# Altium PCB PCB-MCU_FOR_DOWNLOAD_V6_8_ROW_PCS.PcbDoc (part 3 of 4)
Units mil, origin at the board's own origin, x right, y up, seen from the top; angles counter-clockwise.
Board outline not stored, 4 copper layers (Top, GND1, GND2, Bottom), stack 35.4 mil thick; 280 components, 38 nets, 1144 pads, 944 vias.
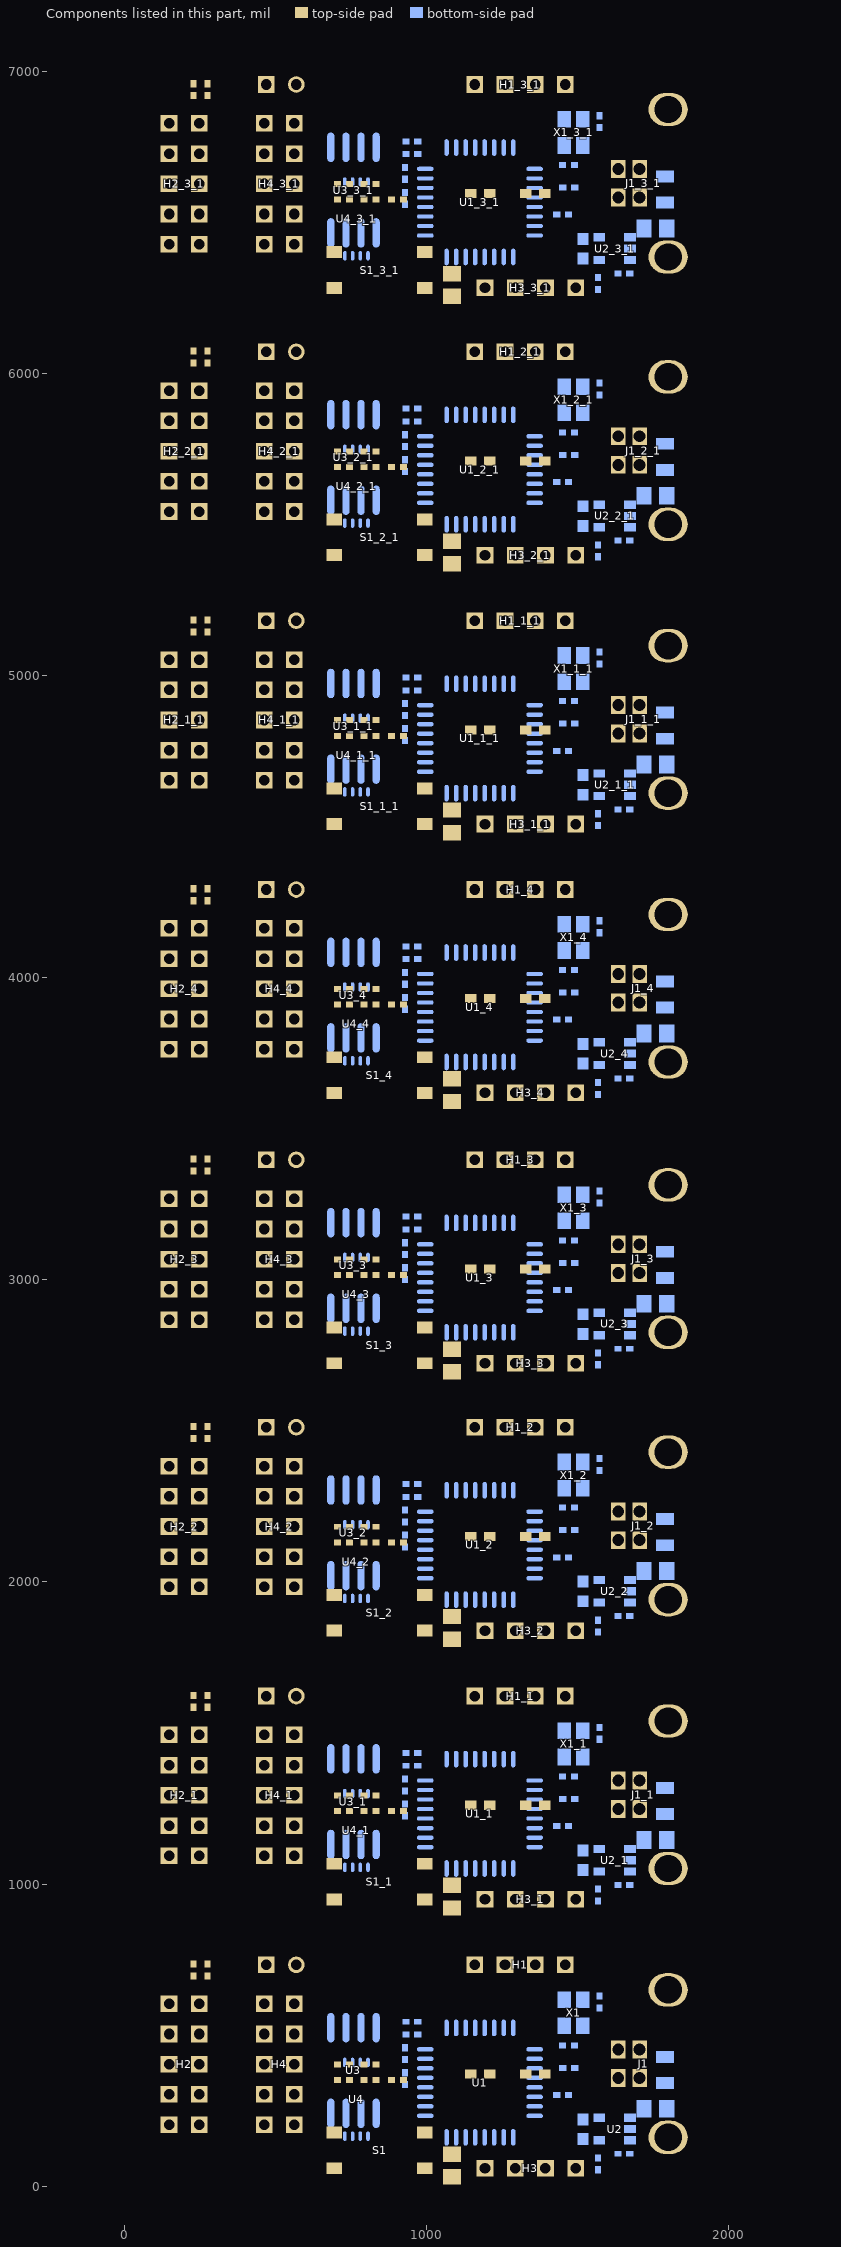
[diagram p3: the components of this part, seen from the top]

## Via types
v1: diameter 16/16/16/16 (per signal layer), hole 8, Top to Bottom, 936 vias
v2: diameter 55/55/55/55 (per signal layer), hole 37, Top to Bottom, 8 vias

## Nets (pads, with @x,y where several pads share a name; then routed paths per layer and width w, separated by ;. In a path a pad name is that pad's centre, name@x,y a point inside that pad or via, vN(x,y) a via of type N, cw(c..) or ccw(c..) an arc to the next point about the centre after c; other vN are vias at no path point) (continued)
copper on no net: (continued)
  Bottom w7.87: 146.85,1393.54 194.88,1441.57 413.78,1441.57 461.81,1393.54 508.27,1440 509.06,1440 509.84,1440.79 582.68,1440.79 601.57,1459.69 601.57,1497.09 637.4,1532.91 878.74,1532.91 966.14,1445.51 966.14,1434.09 966.14,1432.91 968.9,1432.91 970.08,1434.09 970.08,1391.58 970.08,1389.61 928.35,1347.87 ; 146.85,2283.54 194.88,2331.57 413.78,2331.57 461.81,2283.54 508.27,2330 509.06,2330 509.84,2330.79 582.68,2330.79 601.57,2349.69 601.57,2387.09 637.4,2422.91 878.74,2422.91 966.14,2335.51 966.14,2324.09 966.14,2322.91 968.9,2322.91 970.08,2324.09 970.08,2281.58 970.08,2279.61 928.35,2237.87 ; 146.85,3168.54 194.88,3216.57 413.78,3216.57 461.81,3168.54 508.27,3215 509.06,3215 509.84,3215.79 582.68,3215.79 601.57,3234.69 601.57,3272.09 637.4,3307.91 878.74,3307.91 966.14,3220.51 966.14,3209.09 966.14,3207.91 968.9,3207.91 970.08,3209.09 970.08,3166.58 970.08,3164.61 928.35,3122.87 ; 146.85,4063.54 194.88,4111.57 413.78,4111.57 461.81,4063.54 508.27,4110 509.06,4110 509.84,4110.79 582.68,4110.79 601.57,4129.69 601.57,4167.09 637.4,4202.91 878.74,4202.91 966.14,4115.51 966.14,4104.09 966.14,4102.91 968.9,4102.91 970.08,4104.09 970.08,4061.58 970.08,4059.61 928.35,4017.87 ; 146.85,4953.54 194.88,5001.57 413.78,5001.57 461.81,4953.54 508.27,5000 509.06,5000 509.84,5000.79 582.68,5000.79 601.57,5019.69 601.57,5057.09 637.4,5092.91 878.74,5092.91 966.14,5005.51 966.14,4994.09 966.14,4992.91 968.9,4992.91 970.08,4994.09 970.08,4951.58 970.08,4949.61 928.35,4907.87 ; 146.85,5843.54 194.88,5891.57 413.78,5891.57 461.81,5843.54 508.27,5890 509.06,5890 509.84,5890.79 582.68,5890.79 601.57,5909.69 601.57,5947.09 637.4,5982.91 878.74,5982.91 966.14,5895.51 966.14,5884.09 966.14,5882.91 968.9,5882.91 970.08,5884.09 970.08,5841.58 970.08,5839.61 928.35,5797.87 ; 146.85,6728.54 194.88,6776.57 413.78,6776.57 461.81,6728.54 508.27,6775 509.06,6775 509.84,6775.79 582.68,6775.79 601.57,6794.69 601.57,6832.09 637.4,6867.91 878.74,6867.91 966.14,6780.51 966.14,6769.09 966.14,6767.91 968.9,6767.91 970.08,6769.09 970.08,6726.58 970.08,6724.61 928.35,6682.87 ; 461.81,1193.54 511.42,1243.15 511.42,1243.94 598.82,1243.94 638.58,1283.7 638.58,1432.91 638.98,1433.31 638.98,1470.31 661.02,1492.36 753.9,1492.36 785.12,1461.14 785.12,1417.05 782.48,1414.41 782.48,1321.1 v1@782.48,1320.31 ; 461.81,2083.54 511.42,2133.15 511.42,2133.94 598.82,2133.94 638.58,2173.7 638.58,2322.91 638.98,2323.31 638.98,2360.31 661.02,2382.36 753.9,2382.36 785.12,2351.14 785.12,2307.05 782.48,2304.41 782.48,2211.1 v1@782.48,2210.31 ; 461.81,2968.54 511.42,3018.15 511.42,3018.94 598.82,3018.94 638.58,3058.7 638.58,3207.91 638.98,3208.31 638.98,3245.31 661.02,3267.36 753.9,3267.36 785.12,3236.14 785.12,3192.05 782.48,3189.41 782.48,3096.1 v1@782.48,3095.31 ; 461.81,3863.54 511.42,3913.15 511.42,3913.94 598.82,3913.94 638.58,3953.7 638.58,4102.91 638.98,4103.31 638.98,4140.31 661.02,4162.36 753.9,4162.36 785.12,4131.14 785.12,4087.05 782.48,4084.41 782.48,3991.1 v1@782.48,3990.31 ; 461.81,4753.54 511.42,4803.15 511.42,4803.94 598.82,4803.94 638.58,4843.7 638.58,4992.91 638.98,4993.31 638.98,5030.31 661.02,5052.36 753.9,5052.36 785.12,5021.14 785.12,4977.05 782.48,4974.41 782.48,4881.1 v1@782.48,4880.31 ; 461.81,5643.54 511.42,5693.15 511.42,5693.94 598.82,5693.94 638.58,5733.7 638.58,5882.91 638.98,5883.31 638.98,5920.31 661.02,5942.36 753.9,5942.36 785.12,5911.14 785.12,5867.05 782.48,5864.41 782.48,5771.1 v1@782.48,5770.31 ; 461.81,6528.54 511.42,6578.15 511.42,6578.94 598.82,6578.94 638.58,6618.7 638.58,6767.91 638.98,6768.31 638.98,6805.31 661.02,6827.36 753.9,6827.36 785.12,6796.14 785.12,6752.05 782.48,6749.41 782.48,6656.1 v1@782.48,6655.31 ; 463.55,1096.92 464.09,1096.92 465.75,1098.58 466.54,1098.58 507.56,1139.61 587.8,1139.61 728.74,1280.55 728.74,1299.45 728.74,1323.86 692.52,1360.08 v1@692.13,1360.47 ; 463.55,1986.92 464.09,1986.92 465.75,1988.58 466.54,1988.58 507.56,2029.61 587.8,2029.61 728.74,2170.55 728.74,2189.45 728.74,2213.86 692.52,2250.08 v1@692.13,2250.47 ; 463.55,2871.92 464.09,2871.92 465.75,2873.58 466.54,2873.58 507.56,2914.61 587.8,2914.61 728.74,3055.55 728.74,3074.45 728.74,3098.86 692.52,3135.08 v1@692.13,3135.47 ; 463.55,3766.92 464.09,3766.92 465.75,3768.58 466.54,3768.58 507.56,3809.61 587.8,3809.61 728.74,3950.55 728.74,3969.45 728.74,3993.86 692.52,4030.08 v1@692.13,4030.47 ; 463.55,4656.92 464.09,4656.92 465.75,4658.58 466.54,4658.58 507.56,4699.61 587.8,4699.61 728.74,4840.55 728.74,4859.45 728.74,4883.86 692.52,4920.08 v1@692.13,4920.47 ; 463.55,5546.92 464.09,5546.92 465.75,5548.58 466.54,5548.58 507.56,5589.61 587.8,5589.61 728.74,5730.55 728.74,5749.45 728.74,5773.86 692.52,5810.08 v1@692.13,5810.47 ; 463.55,6431.92 464.09,6431.92 465.75,6433.58 466.54,6433.58 507.56,6474.61 587.8,6474.61 728.74,6615.55 728.74,6634.45 728.74,6658.86 692.52,6695.08 v1@692.13,6695.47 ; 561.81,1193.54 575.2,1193.54 575.98,1192.76 658.27,1275.04 658.27,1461.26 673.23,1476.22 715.94,1476.22 732.48,1459.69 732.48,1414.41 733.86,1413.03 733.86,1370.71 754.33,1350.24 754.33,1321.1 v1(753.94,1321.1) 754.33,1320.71 754.33,1299.45 ; 561.81,1493.54 618.11,1549.84 929.53,1549.84 1044.49,1434.88 1044.49,1171.5 1026.77,1153.78 994.88,1153.78 994.09,1154.57 962.6,1154.57 835.83,1027.8 766.54,1027.8 754.33,1040 754.33,1055.35 754.33,1077.8 733.07,1099.06 733.07,1130.35 732.48,1130.94 ; 561.81,2083.54 575.2,2083.54 575.98,2082.76 658.27,2165.04 658.27,2351.26 673.23,2366.22 715.94,2366.22 732.48,2349.69 732.48,2304.41 733.86,2303.03 733.86,2260.71 754.33,2240.24 754.33,2211.1 v1(753.94,2211.1) 754.33,2210.71 754.33,2189.45 ; 561.81,2383.54 618.11,2439.84 929.53,2439.84 1044.49,2324.88 1044.49,2061.5 1026.77,2043.78 994.88,2043.78 994.09,2044.57 962.6,2044.57 835.83,1917.8 766.54,1917.8 754.33,1930 754.33,1945.35 754.33,1967.8 733.07,1989.06 733.07,2020.35 732.48,2020.94 ; 561.81,2968.54 575.2,2968.54 575.98,2967.76 658.27,3050.04 658.27,3236.26 673.23,3251.22 715.94,3251.22 732.48,3234.69 732.48,3189.41 733.86,3188.03 733.86,3145.71 754.33,3125.24 754.33,3096.1 v1(753.94,3096.1) 754.33,3095.71 754.33,3074.45 ; 561.81,3268.54 618.11,3324.84 929.53,3324.84 1044.49,3209.88 1044.49,2946.5 1026.77,2928.78 994.88,2928.78 994.09,2929.57 962.6,2929.57 835.83,2802.8 766.54,2802.8 754.33,2815 754.33,2830.35 754.33,2852.8 733.07,2874.06 733.07,2905.35 732.48,2905.94 ; 561.81,3863.54 575.2,3863.54 575.98,3862.76 658.27,3945.04 658.27,4131.26 673.23,4146.22 715.94,4146.22 732.48,4129.69 732.48,4084.41 733.86,4083.03 733.86,4040.71 754.33,4020.24 754.33,3991.1 v1(753.94,3991.1) 754.33,3990.71 754.33,3969.45 ; 561.81,4163.54 618.11,4219.84 929.53,4219.84 1044.49,4104.88 1044.49,3841.5 1026.77,3823.78 994.88,3823.78 994.09,3824.57 962.6,3824.57 835.83,3697.8 766.54,3697.8 754.33,3710 754.33,3725.35 754.33,3747.8 733.07,3769.06 733.07,3800.35 732.48,3800.94 ; 561.81,4753.54 575.2,4753.54 575.98,4752.76 658.27,4835.04 658.27,5021.26 673.23,5036.22 715.94,5036.22 732.48,5019.69 732.48,4974.41 733.86,4973.03 733.86,4930.71 754.33,4910.24 754.33,4881.1 v1(753.94,4881.1) 754.33,4880.71 754.33,4859.45 ; 561.81,5053.54 618.11,5109.84 929.53,5109.84 1044.49,4994.88 1044.49,4731.5 1026.77,4713.78 994.88,4713.78 994.09,4714.57 962.6,4714.57 835.83,4587.8 766.54,4587.8 754.33,4600 754.33,4615.35 754.33,4637.8 733.07,4659.06 733.07,4690.35 732.48,4690.94 ; 561.81,5643.54 575.2,5643.54 575.98,5642.76 658.27,5725.04 658.27,5911.26 673.23,5926.22 715.94,5926.22 732.48,5909.69 732.48,5864.41 733.86,5863.03 733.86,5820.71 754.33,5800.24 754.33,5771.1 v1(753.94,5771.1) 754.33,5770.71 754.33,5749.45 ; 561.81,5943.54 618.11,5999.84 929.53,5999.84 1044.49,5884.88 1044.49,5621.5 1026.77,5603.78 994.88,5603.78 994.09,5604.57 962.6,5604.57 835.83,5477.8 766.54,5477.8 754.33,5490 754.33,5505.35 754.33,5527.8 733.07,5549.06 733.07,5580.35 732.48,5580.94 ; 561.81,6528.54 575.2,6528.54 575.98,6527.76 658.27,6610.04 658.27,6796.26 673.23,6811.22 715.94,6811.22 732.48,6794.69 732.48,6749.41 733.86,6748.03 733.86,6705.71 754.33,6685.24 754.33,6656.1 v1(753.94,6656.1) 754.33,6655.71 754.33,6634.45 ; 561.81,6828.54 618.11,6884.84 929.53,6884.84 1044.49,6769.88 1044.49,6506.5 1026.77,6488.78 994.88,6488.78 994.09,6489.57 962.6,6489.57 835.83,6362.8 766.54,6362.8 754.33,6375 754.33,6390.35 754.33,6412.8 733.07,6434.06 733.07,6465.35 732.48,6465.94 ; 565.4,1100.1 569.82,1100.1 570.87,1099.06 677.97,1206.16 782.48,1206.16 782.48,1203.78 ; 565.4,1990.1 569.82,1990.1 570.87,1989.06 677.97,2096.16 782.48,2096.16 782.48,2093.78 ; 565.4,2875.1 569.82,2875.1 570.87,2874.06 677.97,2981.16 782.48,2981.16 782.48,2978.78 ; 565.4,3770.1 569.82,3770.1 570.87,3769.06 677.97,3876.16 782.48,3876.16 782.48,3873.78 ; 565.4,4660.1 569.82,4660.1 570.87,4659.06 677.97,4766.16 782.48,4766.16 782.48,4763.78 ; 565.4,5550.1 569.82,5550.1 570.87,5549.06 677.97,5656.16 782.48,5656.16 782.48,5653.78 ; 565.4,6435.1 569.82,6435.1 570.87,6434.06 677.97,6541.16 782.48,6541.16 782.48,6538.78 ; 682.48,1414.41 683.46,1413.43 683.46,1369.13 v1@692.13,1360.47 ; 682.48,2304.41 683.46,2303.43 683.46,2259.13 v1@692.13,2250.47 ; 682.48,3189.41 683.46,3188.43 683.46,3144.13 v1@692.13,3135.47 ; 682.48,4084.41 683.46,4083.43 683.46,4039.13 v1@692.13,4030.47 ; 682.48,4974.41 683.46,4973.43 683.46,4929.13 v1@692.13,4920.47 ; 682.48,5864.41 683.46,5863.43 683.46,5819.13 v1@692.13,5810.47 ; 682.48,6749.41 683.46,6748.43 683.46,6704.13 v1@692.13,6695.47 ; v1(692.91,1187.24) 692.91,1186.65 682.48,1176.22 ; v1(692.91,1360.47) v1@692.13,1360.47 ; v1(692.91,2077.24) 692.91,2076.65 682.48,2066.22 ; v1(692.91,2250.47) v1@692.13,2250.47 ; v1(692.91,2962.24) 692.91,2961.65 682.48,2951.22 ; v1(692.91,3135.47) v1@692.13,3135.47 ; v1(692.91,3857.24) 692.91,3856.65 682.48,3846.22 ; v1(692.91,4030.47) v1@692.13,4030.47 ; v1(692.91,4747.24) 692.91,4746.65 682.48,4736.22 ; v1(692.91,4920.47) v1@692.13,4920.47 ; v1(692.91,5637.24) 692.91,5636.65 682.48,5626.22 ; v1(692.91,5810.47) v1@692.13,5810.47 ; v1(692.91,6522.24) 692.91,6521.65 682.48,6511.22 ; v1(692.91,6695.47) v1@692.13,6695.47 ; 779.92,1055.35 779.92,1109.69 782.48,1112.24 782.48,1130.94 782.48,1203.78 ; 779.92,1299.45 782.48,1302.01 v1@782.48,1320.31 ; 779.92,1945.35 779.92,1999.69 782.48,2002.24 782.48,2020.94 782.48,2093.78 ; 779.92,2189.45 782.48,2192.01 v1@782.48,2210.31 ; 779.92,2830.35 779.92,2884.69 782.48,2887.24 782.48,2905.94 782.48,2978.78 ; 779.92,3074.45 782.48,3077.01 v1@782.48,3095.31 ; 779.92,3725.35 779.92,3779.69 782.48,3782.24 782.48,3800.94 782.48,3873.78 ; 779.92,3969.45 782.48,3972.01 v1@782.48,3990.31 ; 779.92,4615.35 779.92,4669.69 782.48,4672.24 782.48,4690.94 782.48,4763.78 ; 779.92,4859.45 782.48,4862.01 v1@782.48,4880.31 ; 779.92,5505.35 779.92,5559.69 782.48,5562.24 782.48,5580.94 782.48,5653.78 ; 779.92,5749.45 782.48,5752.01 v1@782.48,5770.31 ; 779.92,6390.35 779.92,6444.69 782.48,6447.24 782.48,6465.94 782.48,6538.78 ; 779.92,6634.45 782.48,6637.01 v1@782.48,6655.31 ; v1(783.46,1321.1) 782.68,1320.31 v1@782.48,1320.31 ; v1(783.46,2211.1) 782.68,2210.31 v1@782.48,2210.31 ; v1(783.46,3096.1) 782.68,3095.31 v1@782.48,3095.31 ; v1(783.46,3991.1) 782.68,3990.31 v1@782.48,3990.31 ; v1(783.46,4881.1) 782.68,4880.31 v1@782.48,4880.31 ; v1(783.46,5771.1) 782.68,5770.31 v1@782.48,5770.31 ; v1(783.46,6656.1) 782.68,6655.31 v1@782.48,6655.31 ; v1(791.34,1210.87) 784.25,1203.78 782.48,1203.78 ; v1(791.34,2100.87) 784.25,2093.78 782.48,2093.78 ; v1(791.34,2985.87) 784.25,2978.78 782.48,2978.78 ; v1(791.34,3880.87) 784.25,3873.78 782.48,3873.78 ; v1(791.34,4770.87) 784.25,4763.78 782.48,4763.78 ; v1(791.34,5660.87) 784.25,5653.78 782.48,5653.78 ; v1(791.34,6545.87) 784.25,6538.78 782.48,6538.78 ; 805.51,1055.35 805.51,1082.13 832.48,1109.09 832.48,1130.94 833.07,1131.54 833.07,1162.05 816.93,1178.19 816.93,1247.09 839.76,1269.92 v1(893.7,1269.92) 893.7,1360.47 v1(872.05,1382.13) ; 805.51,1945.35 805.51,1972.13 832.48,1999.09 832.48,2020.94 833.07,2021.54 833.07,2052.05 816.93,2068.19 816.93,2137.09 839.76,2159.92 v1(893.7,2159.92) 893.7,2250.47 v1(872.05,2272.13) ; 805.51,2830.35 805.51,2857.13 832.48,2884.09 832.48,2905.94 833.07,2906.54 833.07,2937.05 816.93,2953.19 816.93,3022.09 839.76,3044.92 v1(893.7,3044.92) 893.7,3135.47 v1(872.05,3157.13) ; 805.51,3725.35 805.51,3752.13 832.48,3779.09 832.48,3800.94 833.07,3801.54 833.07,3832.05 816.93,3848.19 816.93,3917.09 839.76,3939.92 v1(893.7,3939.92) 893.7,4030.47 v1(872.05,4052.13) ; 805.51,4615.35 805.51,4642.13 832.48,4669.09 832.48,4690.94 833.07,4691.54 833.07,4722.05 816.93,4738.19 816.93,4807.09 839.76,4829.92 v1(893.7,4829.92) 893.7,4920.47 v1(872.05,4942.13) ; 805.51,5505.35 805.51,5532.13 832.48,5559.09 832.48,5580.94 833.07,5581.54 833.07,5612.05 816.93,5628.19 816.93,5697.09 839.76,5719.92 v1(893.7,5719.92) 893.7,5810.47 v1(872.05,5832.13) ; 805.51,6390.35 805.51,6417.13 832.48,6444.09 832.48,6465.94 833.07,6466.54 833.07,6497.05 816.93,6513.19 816.93,6582.09 839.76,6604.92 v1(893.7,6604.92) 893.7,6695.47 v1(872.05,6717.13) ; v1(844.49,1224.65) 845.28,1224.65 884.65,1185.28 994.88,1185.28 ; v1(844.49,2114.65) 845.28,2114.65 884.65,2075.28 994.88,2075.28 ; v1(844.49,2999.65) 845.28,2999.65 884.65,2960.28 994.88,2960.28 ; v1(844.49,3894.65) 845.28,3894.65 884.65,3855.28 994.88,3855.28 ; v1(844.49,4784.65) 845.28,4784.65 884.65,4745.28 994.88,4745.28 ; v1(844.49,5674.65) 845.28,5674.65 884.65,5635.28 994.88,5635.28 ; v1(844.49,6559.65) 845.28,6559.65 884.65,6520.28 994.88,6520.28 ; 852.76,1414.41 853.94,1415.59 ; 852.76,2304.41 853.94,2305.59 ; 852.76,3189.41 853.94,3190.59 ; 852.76,4084.41 853.94,4085.59 ; 852.76,4974.41 853.94,4975.59 ; 852.76,5864.41 853.94,5865.59 ; 852.76,6749.41 853.94,6750.59 ; v1(910.63,1391.57) 911.02,1391.57 930.71,1391.57 ; v1(910.63,2281.57) 911.02,2281.57 930.71,2281.57 ; v1(910.63,3166.57) 911.02,3166.57 930.71,3166.57 ; v1(910.63,4061.57) 911.02,4061.57 930.71,4061.57 ; v1(910.63,4951.57) 911.02,4951.57 930.71,4951.57 ; v1(910.63,5841.57) 911.02,5841.57 930.71,5841.57 ; v1(910.63,6726.57) 911.02,6726.57 930.71,6726.57 ; 928.35,1225.83 948.82,1225.83 970.47,1247.48 994.09,1247.48 994.88,1248.27 ; 928.35,1265.2 948.03,1265.2 v1(948.82,1265.98) ; 928.35,1308.5 929.92,1308.5 964.17,1342.76 994.88,1342.76 ; 928.35,2115.83 948.82,2115.83 970.47,2137.48 994.09,2137.48 994.88,2138.27 ; 928.35,2155.2 948.03,2155.2 v1(948.82,2155.98) ; 928.35,2198.5 929.92,2198.5 964.17,2232.76 994.88,2232.76 ; 928.35,3000.83 948.82,3000.83 970.47,3022.48 994.09,3022.48 994.88,3023.27 ; 928.35,3040.2 948.03,3040.2 v1(948.82,3040.98) ; 928.35,3083.5 929.92,3083.5 964.17,3117.76 994.88,3117.76 ; 928.35,3895.83 948.82,3895.83 970.47,3917.48 994.09,3917.48 994.88,3918.27 ; 928.35,3935.2 948.03,3935.2 v1(948.82,3935.98) ; 928.35,3978.5 929.92,3978.5 964.17,4012.76 994.88,4012.76 ; 928.35,4785.83 948.82,4785.83 970.47,4807.48 994.09,4807.48 994.88,4808.27 ; 928.35,4825.2 948.03,4825.2 v1(948.82,4825.98) ; 928.35,4868.5 929.92,4868.5 964.17,4902.76 994.88,4902.76 ; 928.35,5675.83 948.82,5675.83 970.47,5697.48 994.09,5697.48 994.88,5698.27 ; 928.35,5715.2 948.03,5715.2 v1(948.82,5715.98) ; 928.35,5758.5 929.92,5758.5 964.17,5792.76 994.88,5792.76 ; 928.35,6560.83 948.82,6560.83 970.47,6582.48 994.09,6582.48 994.88,6583.27 ; 928.35,6600.2 948.03,6600.2 v1(948.82,6600.98) ; 928.35,6643.5 929.92,6643.5 964.17,6677.76 994.88,6677.76 ; v1(944.88,1037.64) 972.05,1037.64 1011.02,1076.61 1011.02,1083.7 ; v1(944.88,1069.13) 945.28,1069.53 945.28,1104.17 963.39,1122.28 994.88,1122.28 ; v1(944.88,1927.64) 972.05,1927.64 1011.02,1966.61 1011.02,1973.7 ; v1(944.88,1959.13) 945.28,1959.53 945.28,1994.17 963.39,2012.28 994.88,2012.28 ; v1(944.88,2812.64) 972.05,2812.64 1011.02,2851.61 1011.02,2858.7 ; v1(944.88,2844.13) 945.28,2844.53 945.28,2879.17 963.39,2897.28 994.88,2897.28 ; v1(944.88,3707.64) 972.05,3707.64 1011.02,3746.61 1011.02,3753.7 ; v1(944.88,3739.13) 945.28,3739.53 945.28,3774.17 963.39,3792.28 994.88,3792.28 ; v1(944.88,4597.64) 972.05,4597.64 1011.02,4636.61 1011.02,4643.7 ; v1(944.88,4629.13) 945.28,4629.53 945.28,4664.17 963.39,4682.28 994.88,4682.28 ; v1(944.88,5487.64) 972.05,5487.64 1011.02,5526.61 1011.02,5533.7 ; v1(944.88,5519.13) 945.28,5519.53 945.28,5554.17 963.39,5572.28 994.88,5572.28 ; v1(944.88,6372.64) 972.05,6372.64 1011.02,6411.61 1011.02,6418.7 ; v1(944.88,6404.13) 945.28,6404.53 945.28,6439.17 963.39,6457.28 994.88,6457.28 ; 1065.75,1051.42 1065.75,1075.83 v1(1074.41,1084.49) ; 1065.75,1413.62 1065.75,1449.45 1159.06,1542.76 1159.06,1622.28 ; 1065.75,1941.42 1065.75,1965.83 v1(1074.41,1974.49) ; 1065.75,2303.62 1065.75,2339.45 1159.06,2432.76 1159.06,2512.28 ; 1065.75,2826.42 1065.75,2850.83 v1(1074.41,2859.49) ; 1065.75,3188.62 1065.75,3224.45 1159.06,3317.76 1159.06,3397.28 ; 1065.75,3721.42 1065.75,3745.83 v1(1074.41,3754.49) ; 1065.75,4083.62 1065.75,4119.45 1159.06,4212.76 1159.06,4292.28 ; 1065.75,4611.42 1065.75,4635.83 v1(1074.41,4644.49) ; 1065.75,4973.62 1065.75,5009.45 1159.06,5102.76 1159.06,5182.28 ; 1065.75,5501.42 1065.75,5525.83 v1(1074.41,5534.49) ; 1065.75,5863.62 1065.75,5899.45 1159.06,5992.76 1159.06,6072.28 ; 1065.75,6386.42 1065.75,6410.83 v1(1074.41,6419.49) ; 1065.75,6748.62 1065.75,6784.45 1159.06,6877.76 1159.06,6957.28 ; v1(1074.8,1228.58) 1075.2,1228.19 1075.2,1147.87 ; v1(1074.8,2118.58) 1075.2,2118.19 1075.2,2037.87 ; v1(1074.8,3003.58) 1075.2,3003.19 1075.2,2922.87 ; v1(1074.8,3898.58) 1075.2,3898.19 1075.2,3817.87 ; v1(1074.8,4788.58) 1075.2,4788.19 1075.2,4707.87 ; v1(1074.8,5678.58) 1075.2,5678.19 1075.2,5597.87 ; v1(1074.8,6563.58) 1075.2,6563.19 1075.2,6482.87 ; v1(1096.46,1092.76) 1097.24,1091.97 1097.24,1051.42 ; v1(1096.46,1982.76) 1097.24,1981.97 1097.24,1941.42 ; v1(1096.46,2867.76) 1097.24,2866.97 1097.24,2826.42 ; v1(1096.46,3762.76) 1097.24,3761.97 1097.24,3721.42 ; v1(1096.46,4652.76) 1097.24,4651.97 1097.24,4611.42 ; v1(1096.46,5542.76) 1097.24,5541.97 1097.24,5501.42 ; v1(1096.46,6427.76) 1097.24,6426.97 1097.24,6386.42 ; 1097.24,1413.62 1097.24,1447.09 1259.06,1608.9 1259.06,1622.28 ; 1097.24,2303.62 1097.24,2337.09 1259.06,2498.9 1259.06,2512.28 ; 1097.24,3188.62 1097.24,3222.09 1259.06,3383.9 1259.06,3397.28 ; 1097.24,4083.62 1097.24,4117.09 1259.06,4278.9 1259.06,4292.28 ; 1097.24,4973.62 1097.24,5007.09 1259.06,5168.9 1259.06,5182.28 ; 1097.24,5863.62 1097.24,5897.09 1259.06,6058.9 1259.06,6072.28 ; 1097.24,6748.62 1097.24,6782.09 1259.06,6943.9 1259.06,6957.28 ; v1(1127.95,1094.72) 1128.74,1093.94 1128.74,1051.42 ; v1(1127.95,1984.72) 1128.74,1983.94 1128.74,1941.42 ; v1(1127.95,2869.72) 1128.74,2868.94 1128.74,2826.42 ; v1(1127.95,3764.72) 1128.74,3763.94 1128.74,3721.42 ; v1(1127.95,4654.72) 1128.74,4653.94 1128.74,4611.42 ; v1(1127.95,5544.72) 1128.74,5543.94 1128.74,5501.42 ; v1(1127.95,6429.72) 1128.74,6428.94 1128.74,6386.42 ; 1128.74,1413.62 1128.74,1447.48 1240.16,1558.9 1307.09,1558.9 1359.06,1610.87 1359.06,1622.28 ; 1128.74,2303.62 1128.74,2337.48 1240.16,2448.9 1307.09,2448.9 1359.06,2500.87 1359.06,2512.28 ; 1128.74,3188.62 1128.74,3222.48 1240.16,3333.9 1307.09,3333.9 1359.06,3385.87 1359.06,3397.28 ; 1128.74,4083.62 1128.74,4117.48 1240.16,4228.9 1307.09,4228.9 1359.06,4280.87 1359.06,4292.28 ; 1128.74,4973.62 1128.74,5007.48 1240.16,5118.9 1307.09,5118.9 1359.06,5170.87 1359.06,5182.28 ; 1128.74,5863.62 1128.74,5897.48 1240.16,6008.9 1307.09,6008.9 1359.06,6060.87 1359.06,6072.28 ; 1128.74,6748.62 1128.74,6782.48 1240.16,6893.9 1307.09,6893.9 1359.06,6945.87 1359.06,6957.28 ; v1(1149.61,1360.47) 1208.27,1360.47 1208.66,1360.08 1223.23,1374.65 1223.23,1413.62 ; v1(1149.61,2250.47) 1208.27,2250.47 1208.66,2250.08 1223.23,2264.65 1223.23,2303.62 ; v1(1149.61,3135.47) 1208.27,3135.47 1208.66,3135.08 1223.23,3149.65 1223.23,3188.62 ; v1(1149.61,4030.47) 1208.27,4030.47 1208.66,4030.08 1223.23,4044.65 1223.23,4083.62 ; v1(1149.61,4920.47) 1208.27,4920.47 1208.66,4920.08 1223.23,4934.65 1223.23,4973.62 ; v1(1149.61,5810.47) 1208.27,5810.47 1208.66,5810.08 1223.23,5824.65 1223.23,5863.62 ; v1(1149.61,6695.47) 1208.27,6695.47 1208.66,6695.08 1223.23,6709.65 1223.23,6748.62 ; v1(1159.45,1090.79) 1160.24,1090 1160.24,1051.42 ; v1(1159.45,1980.79) 1160.24,1980 1160.24,1941.42 ; v1(1159.45,2865.79) 1160.24,2865 1160.24,2826.42 ; v1(1159.45,3760.79) 1160.24,3760 1160.24,3721.42 ; v1(1159.45,4650.79) 1160.24,4650 1160.24,4611.42 ; v1(1159.45,5540.79) 1160.24,5540 1160.24,5501.42 ; v1(1159.45,6425.79) 1160.24,6425 1160.24,6386.42 ; 1160.24,1413.62 1160.24,1443.54 1254.33,1537.64 1377.56,1537.64 1450.79,1610.87 1459.06,1610.87 1459.45,1610.87 1459.45,1614.02 1459.06,1622.28 ; 1160.24,2303.62 1160.24,2333.54 1254.33,2427.64 1377.56,2427.64 1450.79,2500.87 1459.06,2500.87 1459.45,2500.87 1459.45,2504.02 1459.06,2512.28 ; 1160.24,3188.62 1160.24,3218.54 1254.33,3312.64 1377.56,3312.64 1450.79,3385.87 1459.06,3385.87 1459.45,3385.87 1459.45,3389.02 1459.06,3397.28 ; 1160.24,4083.62 1160.24,4113.54 1254.33,4207.64 1377.56,4207.64 1450.79,4280.87 1459.06,4280.87 1459.45,4280.87 1459.45,4284.02 1459.06,4292.28 ; 1160.24,4973.62 1160.24,5003.54 1254.33,5097.64 1377.56,5097.64 1450.79,5170.87 1459.06,5170.87 1459.45,5170.87 1459.45,5174.02 1459.06,5182.28 ; 1160.24,5863.62 1160.24,5893.54 1254.33,5987.64 1377.56,5987.64 1450.79,6060.87 1459.06,6060.87 1459.45,6060.87 1459.45,6064.02 1459.06,6072.28 ; 1160.24,6748.62 1160.24,6778.54 1254.33,6872.64 1377.56,6872.64 1450.79,6945.87 1459.06,6945.87 1459.45,6945.87 1459.45,6949.02 1459.06,6957.28 ; 1191.73,1051.42 1191.73,1091.18 1222.44,1121.89 v1(1222.44,1122.28) ; v1(1191.73,1378.98) 1191.73,1413.62 ; 1191.73,1941.42 1191.73,1981.18 1222.44,2011.89 v1(1222.44,2012.28) ; v1(1191.73,2268.98) 1191.73,2303.62 ; 1191.73,2826.42 1191.73,2866.18 1222.44,2896.89 v1(1222.44,2897.28) ; v1(1191.73,3153.98) 1191.73,3188.62 ; 1191.73,3721.42 1191.73,3761.18 1222.44,3791.89 v1(1222.44,3792.28) ; v1(1191.73,4048.98) 1191.73,4083.62 ; 1191.73,4611.42 1191.73,4651.18 1222.44,4681.89 v1(1222.44,4682.28) ; v1(1191.73,4938.98) 1191.73,4973.62 ; 1191.73,5501.42 1191.73,5541.18 1222.44,5571.89 v1(1222.44,5572.28) ; v1(1191.73,5828.98) 1191.73,5863.62 ; 1191.73,6386.42 1191.73,6426.18 1222.44,6456.89 v1(1222.44,6457.28) ; v1(1191.73,6713.98) 1191.73,6748.62 ; v1(1222.44,1088.82) 1223.23,1088.03 1223.23,1051.42 ; v1(1222.44,1978.82) 1223.23,1978.03 1223.23,1941.42 ; v1(1222.44,2863.82) 1223.23,2863.03 1223.23,2826.42 ; v1(1222.44,3758.82) 1223.23,3758.03 1223.23,3721.42 ; v1(1222.44,4648.82) 1223.23,4648.03 1223.23,4611.42 ; v1(1222.44,5538.82) 1223.23,5538.03 1223.23,5501.42 ; v1(1222.44,6423.82) 1223.23,6423.03 1223.23,6386.42 ; 1254.72,1051.42 1254.72,1012.05 1297.01,969.76 1297.01,949.26 1300.59,949.26 1292.91,949.06 ; 1254.72,1413.62 1254.72,1433.7 1281.5,1460.47 1473.62,1460.47 1512.99,1499.84 1512.99,1506.93 1512.99,1507.32 1516.22,1507.32 1516.61,1506.93 1543.31,1480.24 1543.31,1479.37 1572.44,1479.37 ; 1254.72,1941.42 1254.72,1902.05 1297.01,1859.76 1297.01,1839.26 1300.59,1839.26 1292.91,1839.06 ; 1254.72,2303.62 1254.72,2323.7 1281.5,2350.47 1473.62,2350.47 1512.99,2389.84 1512.99,2396.93 1512.99,2397.32 1516.22,2397.32 1516.61,2396.93 1543.31,2370.24 1543.31,2369.37 1572.44,2369.37 ; 1254.72,2826.42 1254.72,2787.05 1297.01,2744.76 1297.01,2724.26 1300.59,2724.26 1292.91,2724.06 ; 1254.72,3188.62 1254.72,3208.7 1281.5,3235.47 1473.62,3235.47 1512.99,3274.84 1512.99,3281.93 1512.99,3282.32 1516.22,3282.32 1516.61,3281.93 1543.31,3255.24 1543.31,3254.37 1572.44,3254.37 ; 1254.72,3721.42 1254.72,3682.05 1297.01,3639.76 1297.01,3619.26 1300.59,3619.26 1292.91,3619.06 ; 1254.72,4083.62 1254.72,4103.7 1281.5,4130.47 1473.62,4130.47 1512.99,4169.84 1512.99,4176.93 1512.99,4177.32 1516.22,4177.32 1516.61,4176.93 1543.31,4150.24 1543.31,4149.37 1572.44,4149.37 ; 1254.72,4611.42 1254.72,4572.05 1297.01,4529.76 1297.01,4509.26 1300.59,4509.26 1292.91,4509.06 ; 1254.72,4973.62 1254.72,4993.7 1281.5,5020.47 1473.62,5020.47 1512.99,5059.84 1512.99,5066.93 1512.99,5067.32 1516.22,5067.32 1516.61,5066.93 1543.31,5040.24 1543.31,5039.37 1572.44,5039.37 ; 1254.72,5501.42 1254.72,5462.05 1297.01,5419.76 1297.01,5399.26 1300.59,5399.26 1292.91,5399.06 ; 1254.72,5863.62 1254.72,5883.7 1281.5,5910.47 1473.62,5910.47 1512.99,5949.84 1512.99,5956.93 1512.99,5957.32 1516.22,5957.32 1516.61,5956.93 1543.31,5930.24 1543.31,5929.37 1572.44,5929.37 ; 1254.72,6386.42 1254.72,6347.05 1297.01,6304.76 1297.01,6284.26 1300.59,6284.26 1292.91,6284.06 ; 1254.72,6748.62 1254.72,6768.7 1281.5,6795.47 1473.62,6795.47 1512.99,6834.84 1512.99,6841.93 1512.99,6842.32 1516.22,6842.32 1516.61,6841.93 1543.31,6815.24 1543.31,6814.37 1572.44,6814.37 ; 1286.22,1051.42 1286.22,1013.62 1306.5,993.35 1359.06,993.35 1398.13,954.27 1400.79,951.61 1392.91,949.06 ; 1286.22,1413.62 1286.22,1434.09 1294.88,1442.76 1438.58,1442.76 1455.04,1426.3 1455.04,1420.31 1455.04,1414.33 1449.61,1408.9 1449.61,1355.75 ; 1286.22,1941.42 1286.22,1903.62 1306.5,1883.35 1359.06,1883.35 1398.13,1844.27 1400.79,1841.61 1392.91,1839.06 ; 1286.22,2303.62 1286.22,2324.09 1294.88,2332.76 1438.58,2332.76 1455.04,2316.3 1455.04,2310.31 1455.04,2304.33 1449.61,2298.9 1449.61,2245.75 ; 1286.22,2826.42 1286.22,2788.62 1306.5,2768.35 1359.06,2768.35 1398.13,2729.27 1400.79,2726.61 1392.91,2724.06 ; 1286.22,3188.62 1286.22,3209.09 1294.88,3217.76 1438.58,3217.76 1455.04,3201.3 1455.04,3195.31 1455.04,3189.33 1449.61,3183.9 1449.61,3130.75 ; 1286.22,3721.42 1286.22,3683.62 1306.5,3663.35 1359.06,3663.35 1398.13,3624.27 1400.79,3621.61 1392.91,3619.06 ; 1286.22,4083.62 1286.22,4104.09 1294.88,4112.76 1438.58,4112.76 1455.04,4096.3 1455.04,4090.31 1455.04,4084.33 1449.61,4078.9 1449.61,4025.75 ; 1286.22,4611.42 1286.22,4573.62 1306.5,4553.35 1359.06,4553.35 1398.13,4514.27 1400.79,4511.61 1392.91,4509.06 ; 1286.22,4973.62 1286.22,4994.09 1294.88,5002.76 1438.58,5002.76 1455.04,4986.3 1455.04,4980.31 1455.04,4974.33 1449.61,4968.9 1449.61,4915.75 ; 1286.22,5501.42 1286.22,5463.62 1306.5,5443.35 1359.06,5443.35 1398.13,5404.27 1400.79,5401.61 1392.91,5399.06 ; 1286.22,5863.62 1286.22,5884.09 1294.88,5892.76 1438.58,5892.76 1455.04,5876.3 1455.04,5870.31 1455.04,5864.33 1449.61,5858.9 1449.61,5805.75 ; 1286.22,6386.42 1286.22,6348.62 1306.5,6328.35 1359.06,6328.35 1398.13,6289.27 1400.79,6286.61 1392.91,6284.06 ; 1286.22,6748.62 1286.22,6769.09 1294.88,6777.76 1438.58,6777.76 1455.04,6761.3 1455.04,6755.31 1455.04,6749.33 1449.61,6743.9 1449.61,6690.75 ; v1(1309.06,1342.76) 1357.09,1342.76 ; v1(1309.06,2232.76) 1357.09,2232.76 ; v1(1309.06,3117.76) 1357.09,3117.76 ; v1(1309.06,4012.76) 1357.09,4012.76 ; v1(1309.06,4902.76) 1357.09,4902.76 ; v1(1309.06,5792.76) 1357.09,5792.76 ; v1(1309.06,6677.76) 1357.09,6677.76 ; v1(1311.02,1311.26) 1357.09,1311.26 ; v1(1311.02,2201.26) 1357.09,2201.26 ; v1(1311.02,3086.26) 1357.09,3086.26 ; v1(1311.02,3981.26) 1357.09,3981.26 ; v1(1311.02,4871.26) 1357.09,4871.26 ; v1(1311.02,5761.26) 1357.09,5761.26 ; v1(1311.02,6646.26) 1357.09,6646.26 ; v1(1322.83,1286.06) 1328.6,1280.3 1328.6,1280.01 1328.85,1279.76 1357.09,1279.76 1381.89,1279.76 v1(1395.67,1293.54) ; v1(1322.83,2176.06) 1328.6,2170.3 1328.6,2170.01 1328.85,2169.76 1357.09,2169.76 1381.89,2169.76 v1(1395.67,2183.54) ; v1(1322.83,3061.06) 1328.6,3055.3 1328.6,3055.01 1328.85,3054.76 1357.09,3054.76 1381.89,3054.76 v1(1395.67,3068.54) ; v1(1322.83,3956.06) 1328.6,3950.3 1328.6,3950.01 1328.85,3949.76 1357.09,3949.76 1381.89,3949.76 v1(1395.67,3963.54) ; v1(1322.83,4846.06) 1328.6,4840.3 1328.6,4840.01 1328.85,4839.76 1357.09,4839.76 1381.89,4839.76 v1(1395.67,4853.54) ; v1(1322.83,5736.06) 1328.6,5730.3 1328.6,5730.01 1328.85,5729.76 1357.09,5729.76 1381.89,5729.76 v1(1395.67,5743.54) ; v1(1322.83,6621.06) 1328.6,6615.3 1328.6,6615.01 1328.85,6614.76 1357.09,6614.76 1381.89,6614.76 v1(1395.67,6628.54) ; v1(1425.2,1281.73) 1450,1281.73 1450.39,1281.34 ; v1(1425.2,2171.73) 1450,2171.73 1450.39,2171.34 ; v1(1425.2,3056.73) 1450,3056.73 1450.39,3056.34 ; v1(1425.2,3951.73) 1450,3951.73 1450.39,3951.34 ; v1(1425.2,4841.73) 1450,4841.73 1450.39,4841.34 ; v1(1425.2,5731.73) 1450,5731.73 1450.39,5731.34 ; v1(1425.2,6616.73) 1450,6616.73 1450.39,6616.34 ; 1469.68,1191.58 1489.76,1191.58 v1(1490.16,1191.18) ; 1469.68,2081.58 1489.76,2081.58 v1(1490.16,2081.18) ; 1469.68,2966.58 1489.76,2966.58 v1(1490.16,2966.18) ; 1469.68,3861.58 1489.76,3861.58 v1(1490.16,3861.18) ; 1469.68,4751.58 1489.76,4751.58 v1(1490.16,4751.18) ; 1469.68,5641.58 1489.76,5641.58 v1(1490.16,5641.18) ; 1469.68,6526.58 1489.76,6526.58 v1(1490.16,6526.18) ; 1632.68,997.09 1619.29,1010.47 1617.72,1010.47 1617.72,1088.57 1646.88,1117.73 1647.02,1117.73 1647.24,1117.95 1673.23,1117.95 1674.02,1117.18 1673.23,1116.38 ; 1632.68,1887.09 1619.29,1900.47 1617.72,1900.47 1617.72,1978.57 1646.88,2007.73 1647.02,2007.73 1647.24,2007.95 1673.23,2007.95 1674.02,2007.18 1673.23,2006.38 ; 1632.68,2772.09 1619.29,2785.47 1617.72,2785.47 1617.72,2863.57 1646.88,2892.73 1647.02,2892.73 1647.24,2892.95 1673.23,2892.95 1674.02,2892.18 1673.23,2891.38 ; 1632.68,3667.09 1619.29,3680.47 1617.72,3680.47 1617.72,3758.57 1646.88,3787.73 1647.02,3787.73 1647.24,3787.95 1673.23,3787.95 1674.02,3787.18 1673.23,3786.38 ; 1632.68,4557.09 1619.29,4570.47 1617.72,4570.47 1617.72,4648.57 1646.88,4677.73 1647.02,4677.73 1647.24,4677.95 1673.23,4677.95 1674.02,4677.18 1673.23,4676.38 ; 1632.68,5447.09 1619.29,5460.47 1617.72,5460.47 1617.72,5538.57 1646.88,5567.73 1647.02,5567.73 1647.24,5567.95 1673.23,5567.95 1674.02,5567.18 1673.23,5566.38 ; 1632.68,6332.09 1619.29,6345.47 1617.72,6345.47 1617.72,6423.57 1646.88,6452.73 1647.02,6452.73 1647.24,6452.95 1673.23,6452.95 1674.02,6452.18 1673.23,6451.38 ; v1(1639.76,1078.98) 1673.23,1078.98 1690.94,1078.98 1691.73,1078.19 ; v1(1639.76,1968.98) 1673.23,1968.98 1690.94,1968.98 1691.73,1968.19 ; v1(1639.76,2853.98) 1673.23,2853.98 1690.94,2853.98 1691.73,2853.19 ; v1(1639.76,3748.98) 1673.23,3748.98 1690.94,3748.98 1691.73,3748.19 ; v1(1639.76,4638.98) 1673.23,4638.98 1690.94,4638.98 1691.73,4638.19 ; v1(1639.76,5528.98) 1673.23,5528.98 1690.94,5528.98 1691.73,5528.19 ; v1(1639.76,6413.98) 1673.23,6413.98 1690.94,6413.98 1691.73,6413.19 ; 1672.05,997.09 1673.23,998.27 1673.23,1041.57 v1(1702.76,1041.57) ; 1672.05,1887.09 1673.23,1888.27 1673.23,1931.57 v1(1702.76,1931.57) ; 1672.05,2772.09 1673.23,2773.27 1673.23,2816.57 v1(1702.76,2816.57) ; 1672.05,3667.09 1673.23,3668.27 1673.23,3711.57 v1(1702.76,3711.57) ; 1672.05,4557.09 1673.23,4558.27 1673.23,4601.57 v1(1702.76,4601.57) ; 1672.05,5447.09 1673.23,5448.27 1673.23,5491.57 v1(1702.76,5491.57) ; 1672.05,6332.09 1673.23,6333.27 1673.23,6376.57 v1(1702.76,6376.57) ; v1(1700.79,1069.13) 1691.73,1078.19 ; v1(1700.79,1959.13) 1691.73,1968.19 ; v1(1700.79,2844.13) 1691.73,2853.19 ; v1(1700.79,3739.13) 1691.73,3748.19 ; v1(1700.79,4629.13) 1691.73,4638.19 ; v1(1700.79,5519.13) 1691.73,5528.19 ; v1(1700.79,6404.13) 1691.73,6413.19 ; v1(1702.76,1088.82) 1692.13,1078.19 1691.73,1078.19 ; v1(1702.76,1978.82) 1692.13,1968.19 1691.73,1968.19 ; v1(1702.76,2863.82) 1692.13,2853.19 1691.73,2853.19 ; v1(1702.76,3758.82) 1692.13,3748.19 1691.73,3748.19 ; v1(1702.76,4648.82) 1692.13,4638.19 1691.73,4638.19 ; v1(1702.76,5538.82) 1692.13,5528.19 1691.73,5528.19 ; v1(1702.76,6423.82) 1692.13,6413.19 1691.73,6413.19 ; 682.48,1176.22 686.32,1131.84 682.48,1128 682.48,1130.94 682.48,1176.22 ; 682.48,2066.22 686.32,2021.84 682.48,2018 682.48,2020.94 682.48,2066.22 ; 682.48,2951.22 686.32,2906.84 682.48,2903 682.48,2905.94 682.48,2951.22 ; 682.48,3846.22 686.32,3801.84 682.48,3798 682.48,3800.94 682.48,3846.22 ; 682.48,4736.22 682.48,4690.94 682.48,4688 686.32,4691.84 682.48,4736.22 ; 682.48,5626.22 682.48,5580.94 682.48,5578 686.32,5581.84 682.48,5626.22 ; 682.48,6511.22 682.48,6465.94 682.48,6463 686.32,6466.84 682.48,6511.22
  Bottom w9.84: 1357.09,1153.78 1376.38,1153.78 ; 1357.09,2043.78 1376.38,2043.78 ; 1357.09,2928.78 1376.38,2928.78 ; 1357.09,3823.78 1376.38,3823.78 ; 1357.09,4713.78 1376.38,4713.78 ; 1357.09,5603.78 1376.38,5603.78 ; 1357.09,6488.78 1376.38,6488.78
  Bottom w11.81: 461.81,1093.54 463.55,1096.92 ; 461.81,1983.54 463.55,1986.92 ; 461.81,2868.54 463.55,2871.92 ; 461.81,3763.54 463.55,3766.92 ; 461.81,4653.54 463.55,4656.92 ; 461.81,5543.54 463.55,5546.92 ; 461.81,6428.54 463.55,6431.92 ; 561.81,1093.54 565.4,1097.13 565.4,1100.1 ; 561.81,1393.54 575.72,1393.54 620.08,1437.9 620.08,1485.28 644.88,1510.08 798.43,1510.08 832.48,1476.02 832.48,1414.41 ; 561.81,1983.54 565.4,1987.13 565.4,1990.1 ; 561.81,2283.54 575.72,2283.54 620.08,2327.9 620.08,2375.28 644.88,2400.08 798.43,2400.08 832.48,2366.02 832.48,2304.41 ; 561.81,2868.54 565.4,2872.13 565.4,2875.1 ; 561.81,3168.54 575.72,3168.54 620.08,3212.9 620.08,3260.28 644.88,3285.08 798.43,3285.08 832.48,3251.02 832.48,3189.41 ; 561.81,3763.54 565.4,3767.13 565.4,3770.1 ; 561.81,4063.54 575.72,4063.54 620.08,4107.9 620.08,4155.28 644.88,4180.08 798.43,4180.08 832.48,4146.02 832.48,4084.41 ; 561.81,4653.54 565.4,4657.13 565.4,4660.1 ; 561.81,4953.54 575.72,4953.54 620.08,4997.9 620.08,5045.28 644.88,5070.08 798.43,5070.08 832.48,5036.02 832.48,4974.41 ; 561.81,5543.54 565.4,5547.13 565.4,5550.1 ; 561.81,5843.54 575.72,5843.54 620.08,5887.9 620.08,5935.28 644.88,5960.08 798.43,5960.08 832.48,5926.02 832.48,5864.41 ; 561.81,6428.54 565.4,6432.13 565.4,6435.1 ; 561.81,6728.54 575.72,6728.54 620.08,6772.9 620.08,6820.28 644.88,6845.08 798.43,6845.08 832.48,6811.02 832.48,6749.41 ; 805.51,1299.45 805.51,1345.91 832.68,1373.07 832.68,1414.21 832.48,1414.41 ; 805.51,2189.45 805.51,2235.91 832.68,2263.07 832.68,2304.21 832.48,2304.41 ; 805.51,3074.45 805.51,3120.91 832.68,3148.07 832.68,3189.21 832.48,3189.41 ; 805.51,3969.45 805.51,4015.91 832.68,4043.07 832.68,4084.21 832.48,4084.41 ; 805.51,4859.45 805.51,4905.91 832.68,4933.07 832.68,4974.21 832.48,4974.41 ; 805.51,5749.45 805.51,5795.91 832.68,5823.07 832.68,5864.21 832.48,5864.41 ; 805.51,6634.45 805.51,6680.91 832.68,6708.07 832.68,6749.21 832.48,6749.41 ; 852.76,1414.41 832.48,1414.41 ; 852.76,2304.41 832.48,2304.41 ; 852.76,3189.41 832.48,3189.41 ; 852.76,4084.41 832.48,4084.41 ; 852.76,4974.41 832.48,4974.41 ; 852.76,5864.41 832.48,5864.41 ; 852.76,6749.41 832.48,6749.41 ; 853.94,1415.59 872.44,1434.09 930.71,1434.09 ; 853.94,2305.59 872.44,2324.09 930.71,2324.09 ; 853.94,3190.59 872.44,3209.09 930.71,3209.09 ; 853.94,4085.59 872.44,4104.09 930.71,4104.09 ; 853.94,4975.59 872.44,4994.09 930.71,4994.09 ; 853.94,5865.59 872.44,5884.09 930.71,5884.09 ; 853.94,6750.59 872.44,6769.09 930.71,6769.09 ; 1192.91,949.06 1190.76,949.27 1190.63,949.27 1161.32,978.58 1087.4,978.58 1045.28,1020.71 1044.88,1020.71 1044.88,1085.28 1144.09,1184.49 1151.97,1184.49 1152.76,1185.28 1357.09,1185.28 ; 1192.91,1839.06 1190.76,1839.27 1190.63,1839.27 1161.32,1868.58 1087.4,1868.58 1045.28,1910.71 1044.88,1910.71 1044.88,1975.28 1144.09,2074.49 1151.97,2074.49 1152.76,2075.28 1357.09,2075.28 ; 1192.91,2724.06 1190.76,2724.27 1190.63,2724.27 1161.32,2753.58 1087.4,2753.58 1045.28,2795.71 1044.88,2795.71 1044.88,2860.28 1144.09,2959.49 1151.97,2959.49 1152.76,2960.28 1357.09,2960.28 ; 1192.91,3619.06 1190.76,3619.27 1190.63,3619.27 1161.32,3648.58 1087.4,3648.58 1045.28,3690.71 1044.88,3690.71 1044.88,3755.28 1144.09,3854.49 1151.97,3854.49 1152.76,3855.28 1357.09,3855.28 ; 1192.91,4509.06 1190.76,4509.27 1190.63,4509.27 1161.32,4538.58 1087.4,4538.58 1045.28,4580.71 1044.88,4580.71 1044.88,4645.28 1144.09,4744.49 1151.97,4744.49 1152.76,4745.28 1357.09,4745.28 ; 1192.91,5399.06 1190.76,5399.27 1190.63,5399.27 1161.32,5428.58 1087.4,5428.58 1045.28,5470.71 1044.88,5470.71 1044.88,5535.28 1144.09,5634.49 1151.97,5634.49 1152.76,5635.28 1357.09,5635.28 ; 1192.91,6284.06 1190.76,6284.27 1190.63,6284.27 1161.32,6313.58 1087.4,6313.58 1045.28,6355.71 1044.88,6355.71 1044.88,6420.28 1144.09,6519.49 1151.97,6519.49 1152.76,6520.28 1357.09,6520.28
  Bottom w13.78: 1357.09,1216.77 1609.45,1216.77 1633.46,1240.79 1633.86,1241.18 1633.86,1248.27 ; 1357.09,1248.27 1534.25,1248.27 1551.18,1265.2 1580.71,1294.72 1668.9,1294.72 1704.72,1258.9 1704.72,1248.27 ; 1357.09,2106.77 1609.45,2106.77 1633.46,2130.79 1633.86,2131.18 1633.86,2138.27 ; 1357.09,2138.27 1534.25,2138.27 1551.18,2155.2 1580.71,2184.72 1668.9,2184.72 1704.72,2148.9 1704.72,2138.27 ; 1357.09,2991.77 1609.45,2991.77 1633.46,3015.79 1633.86,3016.18 1633.86,3023.27 ; 1357.09,3023.27 1534.25,3023.27 1551.18,3040.2 1580.71,3069.72 1668.9,3069.72 1704.72,3033.9 1704.72,3023.27 ; 1357.09,3886.77 1609.45,3886.77 1633.46,3910.79 1633.86,3911.18 1633.86,3918.27 ; 1357.09,3918.27 1534.25,3918.27 1551.18,3935.2 1580.71,3964.72 1668.9,3964.72 1704.72,3928.9 1704.72,3918.27 ; 1357.09,4776.77 1609.45,4776.77 1633.46,4800.79 1633.86,4801.18 1633.86,4808.27 ; 1357.09,4808.27 1534.25,4808.27 1551.18,4825.2 1580.71,4854.72 1668.9,4854.72 1704.72,4818.9 1704.72,4808.27 ; 1357.09,5666.77 1609.45,5666.77 1633.46,5690.79 1633.86,5691.18 1633.86,5698.27 ; 1357.09,5698.27 1534.25,5698.27 1551.18,5715.2 1580.71,5744.72 1668.9,5744.72 1704.72,5708.9 1704.72,5698.27 ; 1357.09,6551.77 1609.45,6551.77 1633.46,6575.79 1633.86,6576.18 1633.86,6583.27 ; 1357.09,6583.27 1534.25,6583.27 1551.18,6600.2 1580.71,6629.72 1668.9,6629.72 1704.72,6593.9 1704.72,6583.27 ; v1(1397.64,1185.28) 1424.02,1185.28 1430.32,1191.57 ; v1(1397.64,2075.28) 1424.02,2075.28 1430.32,2081.57 ; v1(1397.64,2960.28) 1424.02,2960.28 1430.32,2966.57 ; v1(1397.64,3855.28) 1424.02,3855.28 1430.32,3861.57 ; v1(1397.64,4745.28) 1424.02,4745.28 1430.32,4751.57 ; v1(1397.64,5635.28) 1424.02,5635.28 1430.32,5641.57 ; v1(1397.64,6520.28) 1424.02,6520.28 1430.32,6526.57
  Bottom w15.75: 1011.02,1083.7 1075.2,1147.87 ; 1011.02,1973.7 1075.2,2037.87 ; 1011.02,2858.7 1075.2,2922.87 ; 1011.02,3753.7 1075.2,3817.87 ; 1011.02,4643.7 1075.2,4707.87 ; 1011.02,5533.7 1075.2,5597.87 ; 1011.02,6418.7 1075.2,6482.87 ; 1357.09,1122.28 1370.87,1122.28 1389.37,1140.79 1376.38,1153.78 ; 1357.09,2012.28 1370.87,2012.28 1389.37,2030.79 1376.38,2043.78 ; 1357.09,2897.28 1370.87,2897.28 1389.37,2915.79 1376.38,2928.78 ; 1357.09,3792.28 1370.87,3792.28 1389.37,3810.79 1376.38,3823.78 ; 1357.09,4682.28 1370.87,4682.28 1389.37,4700.79 1376.38,4713.78 ; 1357.09,5572.28 1370.87,5572.28 1389.37,5590.79 1376.38,5603.78 ; 1357.09,6457.28 1370.87,6457.28 1389.37,6475.79 1376.38,6488.78
  Bottom w19.68: 1389.37,1140.79 1391.14,1142.56 1412.8,1142.56 1430.31,1160.08 1692.05,1160.08 1718.9,1146.07 1719.21,1145.91 ; 1389.37,2030.79 1391.14,2032.56 1412.8,2032.56 1430.31,2050.08 1692.05,2050.08 1718.9,2036.07 1719.21,2035.91 ; 1389.37,2915.79 1391.14,2917.56 1412.8,2917.56 1430.31,2935.08 1692.05,2935.08 1718.9,2921.07 1719.21,2920.91 ; 1389.37,3810.79 1391.14,3812.56 1412.8,3812.56 1430.31,3830.08 1692.05,3830.08 1718.9,3816.07 1719.21,3815.91 ; 1389.37,4700.79 1391.14,4702.56 1412.8,4702.56 1430.31,4720.08 1692.05,4720.08 1718.9,4706.07 1719.21,4705.91 ; 1389.37,5590.79 1391.14,5592.56 1412.8,5592.56 1430.31,5610.08 1692.05,5610.08 1718.9,5596.07 1719.21,5595.91 ; 1389.37,6475.79 1391.14,6477.56 1412.8,6477.56 1430.31,6495.08 1692.05,6495.08 1718.9,6481.07 1719.21,6480.91 ; 1516.93,1046.08 1522.66,1046.08 1527.17,1041.57 1566.54,1041.57 ; 1516.93,1936.08 1522.66,1936.08 1527.17,1931.57 1566.54,1931.57 ; 1516.93,2821.08 1522.66,2821.08 1527.17,2816.57 1566.54,2816.57 ; 1516.93,3716.08 1522.66,3716.08 1527.17,3711.57 1566.54,3711.57 ; 1516.93,4606.08 1522.66,4606.08 1527.17,4601.57 1566.54,4601.57 ; 1516.93,5496.08 1522.66,5496.08 1527.17,5491.57 1566.54,5491.57 ; 1516.93,6381.08 1522.66,6381.08 1527.17,6376.57 1566.54,6376.57 ; 1566.54,983.31 1566.54,1041.57 ; 1566.54,1873.31 1566.54,1931.57 ; 1566.54,2758.31 1566.54,2816.57 ; 1566.54,3653.31 1566.54,3711.57 ; 1566.54,4543.31 1566.54,4601.57 ; 1566.54,5433.31 1566.54,5491.57 ; 1566.54,6318.31 1566.54,6376.57 ; 1570.87,1041.57 1566.54,1041.57 ; 1570.87,1931.57 1566.54,1931.57 ; 1570.87,2816.57 1566.54,2816.57 ; 1570.87,3711.57 1566.54,3711.57 ; 1570.87,4601.57 1566.54,4601.57 ; 1570.87,5491.57 1566.54,5491.57 ; 1570.87,6376.57 1566.54,6376.57
  Bottom w23.62: 246.85,1393.54 277.95,1362.44 279.92,1362.44 298.82,1343.54 511.81,1343.54 561.81,1393.54 ; 246.85,2283.54 277.95,2252.44 279.92,2252.44 298.82,2233.54 511.81,2233.54 561.81,2283.54 ; 246.85,3168.54 277.95,3137.44 279.92,3137.44 298.82,3118.54 511.81,3118.54 561.81,3168.54 ; 246.85,4063.54 277.95,4032.44 279.92,4032.44 298.82,4013.54 511.81,4013.54 561.81,4063.54 ; 246.85,4953.54 277.95,4922.44 279.92,4922.44 298.82,4903.54 511.81,4903.54 561.81,4953.54 ; 246.85,5843.54 277.95,5812.44 279.92,5812.44 298.82,5793.54 511.81,5793.54 561.81,5843.54 ; 246.85,6728.54 277.95,6697.44 279.92,6697.44 298.82,6678.54 511.81,6678.54 561.81,6728.54 ; 1357.09,1185.28 v1(1397.64,1185.28) ; 1357.09,2075.28 v1(1397.64,2075.28) ; 1357.09,2960.28 v1(1397.64,2960.28) ; 1357.09,3855.28 v1(1397.64,3855.28) ; 1357.09,4745.28 v1(1397.64,4745.28) ; 1357.09,5635.28 v1(1397.64,5635.28) ; 1357.09,6520.28 v1(1397.64,6520.28) ; 1489.76,1281.34 1516.14,1281.34 v1(1519.69,1277.8) ; 1489.76,2171.34 1516.14,2171.34 v1(1519.69,2167.8) ; 1489.76,3056.34 1516.14,3056.34 v1(1519.69,3052.8) ; 1489.76,3951.34 1516.14,3951.34 v1(1519.69,3947.8) ; 1489.76,4841.34 1516.14,4841.34 v1(1519.69,4837.8) ; 1489.76,5731.34 1516.14,5731.34 v1(1519.69,5727.8) ; 1489.76,6616.34 1516.14,6616.34 v1(1519.69,6612.8)
  Bottom w27.56: 1674.02,1117.18 1688.98,1132.52 1712.99,1132.52 ; 1674.02,2007.18 1688.98,2022.52 1712.99,2022.52 ; 1674.02,2892.18 1688.98,2907.52 1712.99,2907.52 ; 1674.02,3787.18 1688.98,3802.52 1712.99,3802.52 ; 1674.02,4677.18 1688.98,4692.52 1712.99,4692.52 ; 1674.02,5567.18 1688.98,5582.52 1712.99,5582.52 ; 1674.02,6452.18 1688.98,6467.52 1712.99,6467.52
  Bottom w31.5: v2(1348.03,1056.54) 1400.29,1055.86 1455.51,1111.08 1516.93,1111.08 1565.57,1111.08 1570.87,1116.38 ; v2(1348.03,1946.54) 1400.29,1945.86 1455.51,2001.08 1516.93,2001.08 1565.57,2001.08 1570.87,2006.38 ; v2(1348.03,2831.54) 1400.29,2830.86 1455.51,2886.08 1516.93,2886.08 1565.57,2886.08 1570.87,2891.38 ; v2(1348.03,3726.54) 1400.29,3725.86 1455.51,3781.08 1516.93,3781.08 1565.57,3781.08 1570.87,3786.38 ; v2(1348.03,4616.54) 1400.29,4615.86 1455.51,4671.08 1516.93,4671.08 1565.57,4671.08 1570.87,4676.38 ; v2(1348.03,5506.54) 1400.29,5505.86 1455.51,5561.08 1516.93,5561.08 1565.57,5561.08 1570.87,5566.38 ; v2(1348.03,6391.54) 1400.29,6390.86 1455.51,6446.08 1516.93,6446.08 1565.57,6446.08 1570.87,6451.38 ; 1712.99,1132.52 1718.82,1132.52 1718.9,1135.19 ; 1712.99,2022.52 1718.82,2022.52 1718.9,2025.19 ; 1712.99,2907.52 1718.82,2907.52 1718.9,2910.19 ; 1712.99,3802.52 1718.82,3802.52 1718.9,3805.19 ; 1712.99,4692.52 1718.82,4692.52 1718.9,4695.19 ; 1712.99,5582.52 1718.82,5582.52 1718.9,5585.19 ; 1712.99,6467.52 1718.82,6467.52 1718.9,6470.19 ; 1788.98,1231.34 1718.9,1161.26 1718.9,1146.07 1718.9,1145.91 1718.9,1135.19 ; 1788.98,2121.34 1718.9,2051.26 1718.9,2036.07 1718.9,2035.91 1718.9,2025.19 ; 1788.98,3006.34 1718.9,2936.26 1718.9,2921.07 1718.9,2920.91 1718.9,2910.19 ; 1788.98,3901.34 1718.9,3831.26 1718.9,3816.07 1718.9,3815.91 1718.9,3805.19 ; 1788.98,4791.34 1718.9,4721.26 1718.9,4706.07 1718.9,4705.91 1718.9,4695.19 ; 1788.98,5681.34 1718.9,5611.26 1718.9,5596.07 1718.9,5595.91 1718.9,5585.19 ; 1788.98,6566.34 1718.9,6496.26 1718.9,6481.07 1718.9,6480.91 1718.9,6470.19 ; 1718.9,1135.19 1719.21,1145.91 1718.9,1133.23 1718.9,1135.19 ; 1718.9,2025.19 1719.21,2035.91 1718.9,2023.23 1718.9,2025.19 ; 1718.9,2910.19 1719.21,2920.91 1718.9,2908.23 1718.9,2910.19 ; 1718.9,3805.19 1719.21,3815.91 1718.9,3803.23 1718.9,3805.19 ; 1718.9,4695.19 1718.9,4693.23 1719.21,4705.91 1718.9,4695.19 ; 1718.9,5585.19 1718.9,5583.23 1719.21,5595.91 1718.9,5585.19 ; 1718.9,6470.19 1718.9,6468.23 1719.21,6480.91 1718.9,6470.19
  Bottom w39.37: 1633.86,1342.76 1629.14,1344.78 1628.99,1344.93 1628.99,1398.12 1648.43,1417.56 1744.09,1417.56 1788.98,1372.68 1788.98,1317.95 ; 1633.86,2232.76 1629.14,2234.78 1628.99,2234.93 1628.99,2288.12 1648.43,2307.56 1744.09,2307.56 1788.98,2262.68 1788.98,2207.95 ; 1633.86,3117.76 1629.14,3119.78 1628.99,3119.93 1628.99,3173.12 1648.43,3192.56 1744.09,3192.56 1788.98,3147.68 1788.98,3092.95 ; 1633.86,4012.76 1629.14,4014.78 1628.99,4014.93 1628.99,4068.12 1648.43,4087.56 1744.09,4087.56 1788.98,4042.68 1788.98,3987.95 ; 1633.86,4902.76 1629.14,4904.78 1628.99,4904.93 1628.99,4958.12 1648.43,4977.56 1744.09,4977.56 1788.98,4932.68 1788.98,4877.95 ; 1633.86,5792.76 1629.14,5794.78 1628.99,5794.93 1628.99,5848.12 1648.43,5867.56 1744.09,5867.56 1788.98,5822.68 1788.98,5767.95 ; 1633.86,6677.76 1629.14,6679.78 1628.99,6679.93 1628.99,6733.12 1648.43,6752.56 1744.09,6752.56 1788.98,6707.68 1788.98,6652.95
